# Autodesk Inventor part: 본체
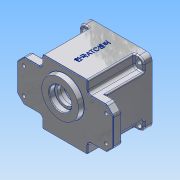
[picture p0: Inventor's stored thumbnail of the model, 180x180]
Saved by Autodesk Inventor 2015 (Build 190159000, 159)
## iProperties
Created: 2016-02
Part Number: 본체
Material: Aluminum 6061
Document SubType Name: Modeling
Designer: Administrator
Density: 2.7 g/cm^3
Appearance: Aluminum - Flat
Mass: 877.68 g
Surface Area: 762.994 cm^2
Volume: 325.067 cm^3
Author: Administrator
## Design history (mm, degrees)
sketch "Sketch1"
  geometry: L1 (47, 47)-(-47, 47); L2 (-47, 47)-(-47, -47); L3 (-47, -47)-(47, -47); L4 (47, -47)-(47, 47); L5 (47, 47)-(-47, -47); L6 (-47, 47)-(47, -47); 1 further point
  constraints: 12 end point, 2 midpoint, 2 parallel, 1 horizontal, 1 perpendicular
  dimensions: "d0" = 94 distance of L3.end L2.end; "d1" = 94 distance of L2.end L1.end
extrude "Extrusion1" new body sketch "Sketch1" distance "d2" = 80; taper "d3" = 0 deg
sketch "Sketch3" dims "d98" = 5
  geometry: L1 (-70, -30)-(70, -30); L2 (70, -30)-(70, 30); L3 (70, 30)-(-70, 30); L4 (-70, 30)-(-70, -30); L5 (-70, -30)-(70, 30); L6 (70, -30)-(-70, 30); 1 further point
  constraints: 12 end point, 2 midpoint, 2 parallel, 1 horizontal, 1 perpendicular
  dimensions: "d4" = 140 distance of L3.end L2.end; "d5" = 60 distance of L2.end L1.end
extrude "Extrusion2" join sketch "Sketch3" distance "d6" = 13; taper "d7" = 0 deg
sketch "Sketch4"
  geometry: C1 r 40 at (0, 0); 1 further point
  constraints: 1 centre point, 1 coincident
  dimensions: "d8" = 80 diameter of C1
extrude "Extrusion3" cut sketch "Sketch4" distance "d9" = 71; taper "d10" = 0 deg
sketch "Sketch5"
  geometry: C1 r 43 at (0, 0); 1 further point
  constraints: 1 centre point, 1 coincident
  dimensions: "d11" = 86 diameter of C1
extrude "Extrusion4" cut sketch "Sketch5" distance "d12" = 9; taper "d13" = 0 deg
sketch "Sketch6"
  geometry: C1 r 2.5 at (60, -19); C2 r 2.5 at (-60, -19); C3 r 2.5 at (60, 19); C4 r 2.5 at (-60, 19); 1 further point
  constraints: 4 centre point, 2 horizontal alignment, 2 vertical alignment
  dimensions: "d14" = 5 diameter of C1; "d15" = 5 diameter of C2; "d16" = 5 diameter of C3; "d17" = 5 diameter of C4; "d18" = 120 distance of C2.centre C1.centre; "d19" = 38 distance of C4.centre C2.centre; "d20" = 19 vertical distance of point (0, 0) C2.centre; "d21" = 60 horizontal distance of point (0, 0) C2.centre
extrude "Extrusion5" cut sketch "Sketch6" stored distance "d22" = 9; taper "d23" = 0 deg
sketch "Sketch7"
  geometry: C1 r 2.5 at (-60, 19) reference; C2 r 2.5 at (-60, -19) reference; C3 r 2.5 at (60, -19) reference; C4 r 2.5 at (60, 19) reference; C5 r 4.5 at (-60, 19); C6 r 4.5 at (60, 19); C7 r 4.5 at (60, -19); C8 r 4.5 at (-60, -19); 1 further point
  constraints: 4 centre point, 4 coincident
  dimensions: "d24" = 9 diameter of C5; "d25" = 9 diameter of C6; "d26" = 9 diameter of C7; "d27" = 9 diameter of C8
extrude "Extrusion6" cut sketch "Sketch7" distance "d28" = 4; taper "d29" = 0 deg
sketch "Sketch9"
  geometry: L1 (70, -30)-(47, -30) reference; L2 (47, 47)-(47, 30) reference; L3 (-47, 47)-(47, 47) reference; L4 (-47, 30)-(-47, 47) reference; L5 (-47, 30)-(-70, 30) reference; L6 (-70, 30)-(-70, -30) reference; L7 (-70, -30)-(-47, -30) reference; L8 (-47, -47)-(-47, -30) reference; L9 (47, -47)-(-47, -47) reference; L10 (47, -30)-(47, -47) reference; L11 (47, -30)-(70, -30) reference; L12 (70, -30)-(70, 30) reference; L13 (70, 30)-(47, 30) reference; L14 (-33, -47)-(-33, -30); L15 (-33, -30)-(-47, -30); L16 (-47, 30)-(-33, 30); L17 (-33, 30)-(-33, 47); L18 (33, 47)-(33, 30); L19 (33, 30)-(47, 30); L20 (47, -30)-(33, -30); L21 (33, -30)-(33, -47); C1 r 40 at (0, 0) reference; C2 r 2.5 at (60, 19) reference; C3 r 2.5 at (60, -19) reference; C4 r 2.5 at (-60, -19) reference; C5 r 2.5 at (-60, 19) reference; 1 further point
  constraints: 16 end point, 8 point on line, 4 perpendicular, 2 horizontal, 2 vertical
  dimensions: "d39" = 66 distance between parallel lines of L14 L21; "d40" = 33 distance from line of point (0, 0) L21; "d41" = 60 distance between parallel lines of L16 L15; "d42" = 30 distance from line of point (0, 0) L16; "d43" = 66 distance between parallel lines of L18 L17; "d44" = 33 distance from line of L18 point (0, 0); "d45" = 60 distance between parallel lines of L20 L19; "d46" = 30 distance from line of point (0, 0) L20
extrude "Extrusion7" cut sketch "Sketch9" distance "d47" = 68; taper "d48" = 0 deg
chamfer "Chamfer1" distance "d49" = 10; stored, may be unused: second distance "d50" = 2, angle "d51" = 45 deg
sketch "Sketch10" dims "d52" = 36
  geometry: A1 r 4 centre (36, 0) between (35.852, 3.997) and (35.852, -3.997); A2 r 40 centre (0, 0) between (39.148, 8.214) and (39.148, -8.214) reference; A3 r 3.5 centre (35.722, -7.495) between (39.148, -8.214) and (35.852, -3.997); A4 r 3.5 centre (35.722, 7.495) between (35.852, 3.997) and (39.148, 8.214); 2 further points
  constraints: 8 point on circle, 4 tangent, 3 centre point, 2 horizontal alignment, 1 coincident, 2 other
  dimensions: "d53" = 4 radius of A1; "d57" = 3.5 radius of A3; "d58" = 3.5 radius of A4
extrude "Extrusion8" join sketch "Sketch10" stored distance "d59" = 67; taper "d60" = 0 deg
mirror "Mirror1"
sketch "Sketch11"
  geometry: A1 r 4 centre (-36, 0) between (-35.852, -3.997) and (-35.852, 3.997) reference; A2 r 4 centre (36, 0) between (35.852, 3.997) and (35.852, -3.997) reference; 3 further points
  constraints: 2 coincident
hole "Hole1" sketch "Sketch11" at (-36, 0), (36, 0) diameter "d61" = 3.242; stored, may be unused: countersink angle "d65" = 90 deg, drill point angle "d67" = 118 deg; dims "d62" = 7, "d63" = 4, "d64" = 2, "d66" = 9
sketch "Sketch12"
  geometry: C1 r 28 at (0, 11); 1 further point
  constraints: 1 centre point, 1 vertical alignment
  dimensions: "d68" = 56 diameter of C1; "d69" = 11 distance of point (0, 0) C1.centre
extrude "Extrusion9" join sketch "Sketch12" distance "d70" = 7; taper "d71" = -10 deg
sketch "Sketch14"
  geometry: C1 r 26.766 at (0, 0) reference; C2 r 16 at (0, 0); 1 further point
  constraints: 1 centre point, 1 coincident
  dimensions: "d75" = 32 diameter of C2
extrude "Extrusion11" cut sketch "Sketch14" distance "d76" = 8; taper "d77" = 0 deg
sketch "Sketch16"
  geometry: C1 r 16 at (0, 11) reference; C2 r 21 at (0, 11); 1 further point
  constraints: 1 centre point, 1 coincident
  dimensions: "d79" = 21 radius of C2
extrude "Extrusion12" join sketch "Sketch16" distance "d80" = 7; taper "d81" = 0 deg
sketch "Sketch17"
  geometry: C1 r 21 at (0, 0) reference; C2 r 17.5 at (0, 0); 1 further point
  constraints: 1 centre point, 1 coincident
  dimensions: "d82" = 35 diameter of C2
extrude "Extrusion13" cut sketch "Sketch17" distance "d83" = 10; taper "d84" = 0 deg
sketch "Sketch18"
  geometry: C1 r 15 at (0, -20); 1 further point
  constraints: 1 centre point, 1 vertical alignment
  dimensions: "d85" = 15 radius of C1; "d86" = 20 distance of C1.centre point (0, 0)
extrude "Extrusion14" join sketch "Sketch18" distance "d87" = 7; taper "d88" = 0 deg
sketch "Sketch20"
  geometry: C1 r 17.5 at (0, 11) reference; C2 r 17.5 at (0, 11); 1 further point
  constraints: 1 centre point, 1 coincident
  dimensions: "d89" = 17.5 radius of C2
extrude "Extrusion15" cut sketch "Sketch20" distance "d90" = 7; taper "d91" = 0 deg
sketch "Sketch21"
  geometry: C1 r 17.5 at (0, 11) reference; C2 r 9.5 at (0, -20); A1 r 21 centre (0, 11) between (8.978, -7.984) and (-8.978, -7.984) reference; A2 r 15 centre (0, -20) between (-8.978, -7.984) and (8.978, -7.984) reference; 1 further point
  constraints: 1 centre point, 1 coincident
  dimensions: "d92" = 19 diameter of C2
extrude "Extrusion16" cut sketch "Sketch21" distance "d93" = 8; taper "d94" = 0 deg
sketch "Sketch22"
  geometry: C1 r 9.5 at (0, -20) reference; C2 r 17.5 at (0, 11) reference; C3 r 11 at (0, -20); A1 r 21 centre (0, 11) between (8.978, -7.984) and (-8.978, -7.984) reference; A2 r 15 centre (0, -20) between (-8.978, -7.984) and (8.978, -7.984) reference; 1 further point
  constraints: 1 centre point, 1 coincident
  dimensions: "d95" = 22 diameter of C3
extrude "Extrusion17" cut sketch "Sketch22" distance "d96" = 7; taper "d97" = 0 deg
fillet "Fillet1" dims "d98" = 5
fillet "Fillet2" dims "d99" = 8
fillet "Fillet3" dims "d100" = 2
fillet "Fillet4" dims "d101" = 2
fillet "Fillet5" dims "d102" = 2
fillet "Fillet6" dims "d103" = 2
sketch "Sketch24"
  geometry: C1 r 16 at (0, 0) reference; C2 r 12.5 at (0, 0); 1 further point
  constraints: 1 centre point, 1 coincident
  dimensions: "d110" = 25 diameter of C2
extrude "Extrusion19" cut sketch "Sketch24" stored distance "d111" = 7; taper "d112" = 0 deg
fillet "Fillet7" dims "d116" = 0.3
fillet "Fillet8" dims "d117" = 2
fillet "Fillet9" dims "d118" = 3
fillet "Fillet10" dims "d119" = 2
fillet "Fillet11" dims "d120" = 2
fillet "Fillet12" dims "d121" = 2
fillet "Fillet13" dims "d122" = 2
sketch "Sketch25"
  geometry: L1 (31, -47)-(-31, -47) reference; L2 (33, -45)-(33, -35) reference; L3 (38, -30)-(60, -30) reference; L4 (70, -20)-(60, -30) reference; L5 (70, -20)-(70, 20) reference; L6 (60, 30)-(70, 20) reference; L7 (60, 30)-(38, 30) reference; L8 (33, 35)-(33, 45) reference; L9 (-31, 47)-(31, 47) reference; L10 (-33, 45)-(-33, 35) reference; L11 (-38, 30)-(-60, 30) reference; L12 (-70, 20)-(-60, 30) reference; L13 (-70, 20)-(-70, -20) reference; L14 (-60, -30)-(-70, -20) reference; L15 (-60, -30)-(-38, -30) reference; L16 (-33, -35)-(-33, -45) reference; L17 (-32, -45)-(-32, -35); L18 (-38, -29)-(-59.586, -29); L19 (-59.586, -29)-(-69, -19.586); L20 (-69, -19.586)-(-69, 19.586); L21 (-69, 19.586)-(-59.586, 29); L22 (-59.586, 29)-(-38, 29); L23 (-32, 35)-(-32, 45); L24 (-31, 46)-(31, 46); L25 (32, 45)-(32, 35); L26 (38, 29)-(59.586, 29); L27 (59.586, 29)-(69, 19.586); L28 (69, 19.586)-(69, -19.586); L29 (69, -19.586)-(59.586, -29); L30 (59.586, -29)-(38, -29); L31 (32, -35)-(32, -45); L32 (31, -46)-(-31, -46); C1 r 2.5 at (-60, 19) reference; C2 r 2.5 at (-60, -19) reference; C3 r 2.5 at (60, -19) reference; C4 r 2.5 at (60, 19) reference; C5 r 28 at (0, 11) reference; A1 r 2 centre (-31, -45) between (-33, -45) and (-31, -47) reference; A2 r 2 centre (31, -45) between (31, -47) and (33, -45) reference; A3 r 5 centre (38, -35) between (38, -30) and (33, -35) reference; A4 r 5 centre (38, 35) between (33, 35) and (38, 30) reference; A5 r 2 centre (31, 45) between (33, 45) and (31, 47) reference; A6 r 2 centre (-31, 45) between (-31, 47) and (-33, 45) reference; A7 r 5 centre (-38, 35) between (-38, 30) and (-33, 35) reference; A8 r 5 centre (-38, -35) between (-33, -35) and (-38, -30) reference; A9 r 1 centre (-31, -45) between (-32, -45) and (-31, -46); A10 r 6 centre (-38, -35) between (-32, -35) and (-38, -29); A11 r 6 centre (-38, 35) between (-38, 29) and (-32, 35); A12 r 1 centre (-31, 45) between (-31, 46) and (-32, 45); A13 r 1 centre (31, 45) between (32, 45) and (31, 46); A14 r 6 centre (38, 35) between (32, 35) and (38, 29); A15 r 6 centre (38, -35) between (38, -29) and (32, -35); A16 r 1 centre (31, -45) between (31, -46) and (32, -45); 1 further point
  constraints: 32 end point, 16 point on circle, 8 centre point, 23 other
  dimensions: "d123" = 1 distance between parallel lines of L1 L32
extrude "Extrusion20" cut sketch "Sketch25" distance "d124" = 1; taper "d125" = 0 deg
chamfer "Chamfer3" distance "d126" = 1; stored, may be unused: second distance "d127" = 2, angle "d128" = 45 deg
sketch "Sketch26"
  geometry: L1 (78, 0)-(0, 0) reference; 2 further points
  constraints: 1 vertical alignment, 1 other
  dimensions: "d129" = 40 distance from line of point (39, 40) L1
emboss "Emboss1" sketch "Sketch26" dims "d130" = 0.5, "d131" = 0
sketch "Sketch27"
  geometry: C1 r 3.5 at (40, -40); C2 r 3.5 at (-40, -40); C3 r 3.5 at (-40, 40); C4 r 3.5 at (40, 40); 1 further point
  constraints: 4 centre point, 2 horizontal alignment, 2 vertical alignment
  dimensions: "d132" = 7 diameter of C1; "d133" = 7 diameter of C2; "d134" = 7 diameter of C3; "d135" = 7 diameter of C4; "d136" = 80 distance of C2.centre C1.centre; "d137" = 80 distance of C3.centre C2.centre; "d138" = 40 horizontal distance of point (0, 0) C2.centre; "d139" = 40 horizontal distance of point (0, 0) C2.centre
extrude "Extrusion21" cut sketch "Sketch27" stored distance "d140" = 1; taper "d141" = 0 deg
fillet "Fillet14" dims "d142" = 5
chamfer "Chamfer4" distance "d143" = 1; stored, may be unused: second distance "d144" = 2, angle "d145" = 45 deg
fillet "Fillet15" dims "d146" = 0.3
body "Solid1"
node "Projected Loop2"
node "Projected Loop3"
node "Projected Loop4"
node "Projected Loop6"
node "Projected Loop7"
node "Projected Loop8"
node "Projected Loop13"
node "Projected Loop14"
